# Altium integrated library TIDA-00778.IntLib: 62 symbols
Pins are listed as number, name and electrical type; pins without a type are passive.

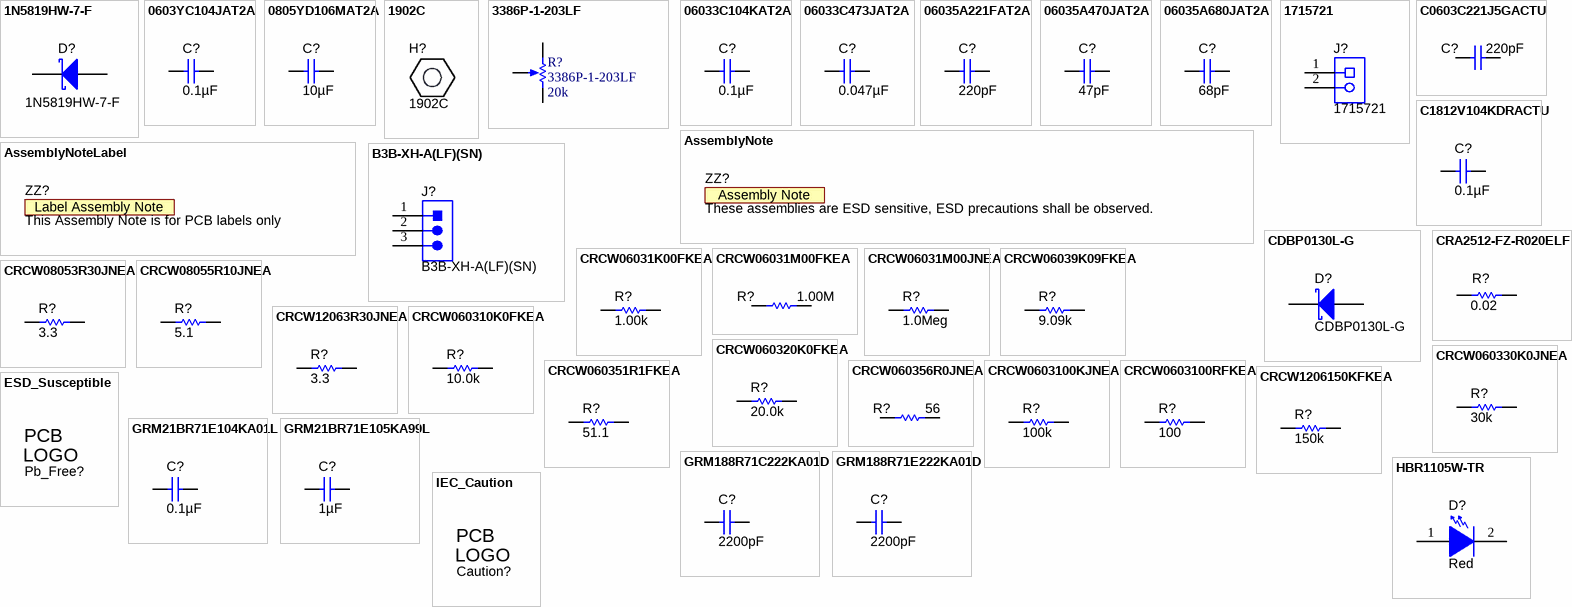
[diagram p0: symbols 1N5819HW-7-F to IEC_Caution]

## 1N5819HW-7-F
designator D?
Diode, Schottky, 40V, 1A, SOD-123; Manufacturer: Diodes Inc.; U/M: EA; Vf_V: 0.45; Value2: 0.45V; Io_A: 1; Vr_V: 40; TJmax_C: 125
signal-integrity model Diode
simulation model DI_1N5819HW
footprint SOD-123
pins: 1 K, 2 A

## 0603YC104JAT2A
designator C?  ValueDisplayed: 0.1µF  (hidden comment: 0603YC104JAT2A)
CAP, CERM, 0.1 µF, 16 V, +/- 5%, X7R, 0603; Manufacturer: AVX; Polarized: N; CompType: Capacitor; Value: 0.1uF; U/M: EA; Cap_F: 0.0000001; Tolerance_%: 5; ESR_ohm: 0.039; Value1: 0.039 ohm; VDC_V: 16; Value2: 16V; TaMin_C: -55; TaMax_C: 125; Cap_Case: 0603
signal-integrity model Cap
simulation model Cap
footprint 0603
footprint 0603M
footprint 0603L
footprint 0603_HV
footprint 0603S
pins: 1, 2

## 0805YD106MAT2A
designator C?  ValueDisplayed: 10µF  (hidden comment: 0805YD106MAT2A)
CAP, CERM, 10 µF, 16 V, +/- 20%, X5R, 0805; Manufacturer: AVX; Polarized: N; CompType: Capacitor; Value: 10uF; U/M: EA; Cap_F: 0.00001; Tolerance_%: 20; Value1: Unknown; VDC_V: 16; Value2: 16V; TaMin_C: -55; TaMax_C: 85; Cap_Case: 0805; SizeArea_mm2: 2.5; SizeAreaWB_mm2: 6.75; SizeX_mm: 2; SizeY_mm: 1.25; SizeZ_mm: 1.45; AEC Category: Q200
signal-integrity model Cap
simulation model Cap
footprint 0805_HV
footprint 0805_HV1
footprint 0805
footprint 0805M
footprint 0805L
pins: 1, 2

## 1902C
designator H?
Standoff, Hex, 0.5"L #4-40 Nylon; Manufacturer: Keystone; CompType: Hardware
footprint Keystone_1902C

## 3386P-1-203LF
designator R?  value 20k
TRIMMER, 20k ohm, 0.5W, TH; Manufacturer: Bourns; Sim Note: Enter the Resistance value and the set point into parameter fields.; SymbolCreator: a0412235
simulation model POT (Potentiometer)
footprint BOURNS_3386P
pins: 1 CCW, 2 WIPER, 3 CW
1 alternate drawing of the same symbol

## 06033C104KAT2A
designator C?  ValueDisplayed: 0.1µF  (hidden comment: 06033C104KAT2A)
CAP, CERM, 0.1 µF, 25 V, +/- 10%, X7R, 0603; Manufacturer: AVX; Polarized: N; CompType: Capacitor; Value: 0.1uF; U/M: EA; Cap_F: 0.0000001; Tolerance_%: 10; ESR_ohm: 0.05; Value1: 0.05 ohm; VDC_V: 25; Value2: 25V; TaMin_C: -55; TaMax_C: 125; Cap_Case: 0603
signal-integrity model Cap
simulation model Cap
footprint 0603
footprint 0603M
footprint 0603L
footprint 0603_HV
footprint 0603S
pins: 1, 2

## 06033C473JAT2A
designator C?  ValueDisplayed: 0.047µF  (hidden comment: 06033C473JAT2A)
CAP, CERM, 0.047 µF, 25 V, +/- 5%, X7R, 0603; Manufacturer: AVX; Polarized: N; CompType: Capacitor; Value: 0.047uF; U/M: EA; Cap_F: 0.000000047; Tolerance_%: 5; ESR_ohm: 0.052; Value1: 0.052 ohm; VDC_V: 25; Value2: 25V; TaMin_C: -55; TaMax_C: 125; Cap_Case: 0603; SizeArea_mm2: 1.28; SizeAreaWB_mm2: 4.68; SizeX_mm: 1.6; SizeY_mm: 0.8; SizeZ_mm: 1; AEC Category: Q200
signal-integrity model Cap
simulation model Cap
footprint 0603
footprint 0603M
footprint 0603L
footprint 0603_HV
footprint 0603S
pins: 1, 2

## 06035A221FAT2A
designator C?  ValueDisplayed: 220pF  (hidden comment: 06035A221FAT2A)
CAP, CERM, 220 pF, 50 V, +/- 1%, C0G/NP0, 0603; Manufacturer: AVX; Polarized: N; CompType: Capacitor; Value: 220pF; U/M: EA; Cap_F: 0.00000000022; Tolerance_%: 1; ESR_ohm: 0.083; Value1: 0.083 ohm; VDC_V: 50; Value2: 50V; TaMin_C: -55; TaMax_C: 125; Cap_Case: 0603
signal-integrity model Cap
simulation model Cap
footprint 0603
footprint 0603M
footprint 0603L
footprint 0603_HV
footprint 0603S
pins: 1, 2

## 06035A470JAT2A
designator C?  ValueDisplayed: 47pF  (hidden comment: 06035A470JAT2A)
CAP, CERM, 47 pF, 50 V, +/- 5%, C0G/NP0, 0603; Manufacturer: AVX; Polarized: N; CompType: Capacitor; Value: 47pF; U/M: EA; Cap_F: 0.000000000047; Tolerance_%: 5; ESR_ohm: 0.174; Value1: 0.174 ohm; VDC_V: 50; Value2: 50V; TaMin_C: -55; TaMax_C: 125; Cap_Case: 0603
signal-integrity model Cap
simulation model Cap
footprint 0603
footprint 0603M
footprint 0603L
footprint 0603_HV
footprint 0603S
pins: 1, 2

## 06035A680JAT2A
designator C?  ValueDisplayed: 68pF  (hidden comment: 06035A680JAT2A)
CAP, CERM, 68pF, 50V, +/-5%, C0G/NP0, 0603; Manufacturer: AVX; Polarized: N; CompType: Capacitor; U/M: EA; Cap_F: 0.000000000068; Tolerance_%: 5; ESR_Ohm: 0.144; Value1: 0.144 ohm; VDC_V: 50; TaMin_C: -55; TaMax_C: 125; Cap_Case: 0603
signal-integrity model Cap
simulation model Cap
footprint 0603
footprint 0603M
footprint 0603L
footprint 0603_HV
footprint 0603S
pins: 1, 2

## 1715721
designator J?
Conn Term Block, 2POS, 5.08mm, TH; Manufacturer: Phoenix Contact; SymbolCreator: a0412235; CompType: Terminal Block; U/M: EA; Value: 2x1
footprint PhoenixContact_1715721
pins: 1, 2

## AssemblyNote
designator ZZ?, comment These assemblies are ESD sensitive, ESD precautions shall be observed.  (no BOM)
SymbolCreator: codlsc; CompType: AssemblyNote
footprint AssemblyNote

## AssemblyNoteLabel
designator ZZ?, comment This Assembly Note is for PCB labels only  (no BOM)
SymbolCreator: a0412235
footprint AssemblyNoteLabel

## B3B-XH-A(LF)(SN)
designator J?
Header (Shrouded), 2.5mm, 3x1, Tin, TH; Manufacturer: JST Manufacturing; SymbolCreator: a0799628; Pitch_mm: 2.5; Gender: Male; Shrouded: Y; Row_Count: 1; Current_A: 3; Voltage_V: 250
footprint JST_B3B-XH-A
pins: 1, 2, 3
3 alternate drawings of the same symbol

## C0603C221J5GACTU
designator C?  ValueDisplayed: 220pF  (hidden comment: C0603C221J5GACTU)
CAP, CERM, 220 pF, 50 V, +/- 5%, C0G/NP0, 0603; Manufacturer: Kemet; Polarized: N; CompType: Capacitor; Value: 220pF; U/M: EA; Cap_F: 0.00000000022; Tolerance_%: 5; Value1: Unknown; VDC_V: 50; Value2: 50V; TaMin_C: -55; TaMax_C: 125; Cap_Case: 0603; SizeArea_mm2: 1.28; SizeAreaWB_mm2: 4.68; SizeX_mm: 1.6; SizeY_mm: 0.8; SizeZ_mm: 1; AEC Category: Q200
signal-integrity model Cap
simulation model Cap
footprint 0603
footprint 0603M
footprint 0603L
footprint 0603_HV
footprint 0603S
pins: 1, 2

## C1812V104KDRACTU
designator C?  ValueDisplayed: 0.1µF  (hidden comment: C1812V104KDRACTU)
CAP, CERM, 0.1 µF, 1000 V, +/- 10%, X7R, 1812; Manufacturer: Kemet; Polarized: N; CompType: Capacitor; Value: 0.1uF; U/M: EA; Cap_F: 0.0000001; Tolerance_%: 10; Value1: Unknown; VDC_V: 1000; Value2: 1000V; TaMin_C: -55; TaMax_C: 125; Cap_Case: 1812; SizeArea_mm2: 14.4; SizeAreaWB_mm2: 23.1; SizeX_mm: 4.5; SizeY_mm: 3.2; SizeZ_mm: 2.54; AEC Category: Q200
signal-integrity model Cap
simulation model Cap
footprint 1812_254
pins: 1, 2

## CDBP0130L-G
designator D?
Diode, Schottky, 30 V, 0.1 A, SOD-723; Manufacturer: Comchip Technology; U/M: EA; Vf_V: 0.35; Value: 30V; Value1: 0.1A; Value2: 0.35V; Io_A: 0.1; Vr_V: 30; TJmax_C: 125; SizeAreaWB_mm2: 3.84; SizeArea_mm2: 0.84; SizeX_mm: 1.4; SizeY_mm: 0.6; SizeZ_mm: 0.65; AEC Category: Q101
signal-integrity model Diode
footprint SOD-723
pins: 1 K, 2 A

## CRA2512-FZ-R020ELF
designator R?  ValueDisplayed: 0.02  (hidden comment: CRA2512-FZ-R020ELF)
RES, 0.02, 1%, 3 W, 2512; Manufacturer: Bourns; CompType: Resistor; Value: 0.02; Value_Code: R020; Tolerance_%: 1; Power_W: 3; Value2: 3W; TempCo: 75 ppm/C; EIA_Code: E96; U/M: EA
signal-integrity model Resistor
simulation model Resistor
footprint 2512
footprint 2512M
footprint 2512L
pins: 1, 2

## CRCW06031K00FKEA
designator R?  ValueDisplayed: 1.00k  (hidden comment: CRCW06031K00FKEA)
RES, 1.00 k, 1%, 0.1 W, 0603; Manufacturer: Vishay-Dale; CompType: Resistor; Value: 1.00k; Res_ohm: 1000; Value_Code: 1k00; Tolerance_%: 1; Power_W: 0.1; Value2: 0.1W; VDC_V: 75; TempCo: 100 ppm/C; EIA_Code: E96; U/M: EA
signal-integrity model Resistor
simulation model Resistor
footprint 0603
footprint 0603M
footprint 0603L
footprint 0603_HV
footprint 0603S
pins: 1, 2

## CRCW06031M00FKEA
designator R?  ValueDisplayed: 1.00M  (hidden comment: CRCW06031M00FKEA)
RES, 1.00 M, 1%, 0.1 W, 0603; Manufacturer: Vishay-Dale; CompType: Resistor; Value: 1.00Meg; Res_ohm: 1000000; Value_Code: 1M00; Tolerance_%: 1; Power_W: 0.1; Value2: 0.1W; VDC_V: 75; TempCo: 100 ppm/C; SizeArea_mm2: 1.28; SizeX_mm: 1.6; SizeY_mm: 0.8; EIA_Code: E96; U/M: EA; AEC Category: Q200
signal-integrity model Resistor
simulation model Resistor
footprint 0603
footprint 0603M
footprint 0603L
footprint 0603_HV
footprint 0603S
pins: 1, 2

## CRCW06031M00JNEA
designator R?  value 1.0Meg  (hidden comment: CRCW06031M00JNEA)
RES, 1.0Meg ohm, 5%, 0.1W, 0603; Manufacturer: Vishay-Dale; CompType: Resistor; Res_ohm: 1000000; Value_Code: 1M00; Tolerance_%: 5; Power_W: 0.1; VDC_V: 75; TempCo: 200 ppm/C; EIA_Code: E24; U/M: EA
signal-integrity model Resistor
simulation model Resistor
footprint 0603
footprint 0603M
footprint 0603L
footprint 0603_HV
footprint 0603S
pins: 1, 2

## CRCW06039K09FKEA
designator R?  ValueDisplayed: 9.09k  (hidden comment: CRCW06039K09FKEA)
RES, 9.09 k, 1%, 0.1 W, 0603; Manufacturer: Vishay-Dale; CompType: Resistor; Res_ohm: 9090; Value: 9.09k; Value_Code: 9k09; Tolerance_%: 1; Power_W: 0.1; Value2: 0.1W; VDC_V: 75; TempCo: 100 ppm/C; EIA_Code: E96; U/M: EA; SizeArea_mm2: 1.28; SizeX_mm: 1.6; SizeY_mm: 0.8; AEC Category: Q200
signal-integrity model Resistor
simulation model Resistor
footprint 0603
footprint 0603M
footprint 0603L
footprint 0603_HV
footprint 0603S
pins: 1, 2

## CRCW08053R30JNEA
designator R?  value 3.3  (hidden comment: CRCW08053R30JNEA)
RES, 3.3 ohm, 5%, 0.125W, 0805; Manufacturer: Vishay-Dale; CompType: Resistor; Value_Code: 3R30; Tolerance_%: 5; Power_W: 0.125; VDC_V: 150; TempCo: 200 ppm/C; EIA_Code: E24; U/M: EA
signal-integrity model Resistor
simulation model Resistor
footprint 0805_HV
footprint 0805
footprint 0805M
footprint 0805L
pins: 1, 2

## CRCW08055R10JNEA
designator R?  value 5.1  (hidden comment: CRCW08055R10JNEA)
RES, 5.1 ohm, 5%, 0.125W, 0805; Manufacturer: Vishay-Dale; CompType: Resistor; Value_Code: 5R10; Tolerance_%: 5; Power_W: 0.125; VDC_V: 150; TempCo: 200 ppm/C; EIA_Code: E24; U/M: EA
signal-integrity model Resistor
simulation model Resistor
footprint 0805_HV
footprint 0805
footprint 0805M
footprint 0805L
pins: 1, 2

## CRCW12063R30JNEA
designator R?  value 3.3  (hidden comment: CRCW12063R30JNEA)
RES, 3.3 ohm, 5%, 0.25W, 1206; Manufacturer: Vishay-Dale; CompType: Resistor; Value_Code: 3R30; Tolerance_%: 5; Power_W: 0.25; VDC_V: 200; TempCo: 200 ppm/C; EIA_Code: E24; U/M: EA
signal-integrity model Resistor
simulation model Resistor
footprint 1206
footprint 1206M
footprint 1206L
pins: 1, 2

## CRCW060310K0FKEA
designator R?  ValueDisplayed: 10.0k  (hidden comment: CRCW060310K0FKEA)
RES, 10.0 k, 1%, 0.1 W, 0603; Manufacturer: Vishay-Dale; CompType: Resistor; Value: 10.0k; Res_ohm: 10000; Value_Code: 10k0; Tolerance_%: 1; Power_W: 0.1; Value2: 0.1W; VDC_V: 75; TempCo: 100 ppm/C; EIA_Code: E96; U/M: EA; SizeArea_mm2: 1.28; SizeX_mm: 1.6; SizeY_mm: 0.8; AEC Category: Q200
signal-integrity model Resistor
simulation model Resistor
footprint 0603
footprint 0603M
footprint 0603L
footprint 0603_HV
footprint 0603S
pins: 1, 2

## CRCW060320K0FKEA
designator R?  value 20.0k  (hidden comment: CRCW060320K0FKEA)
RES, 20.0k ohm, 1%, 0.1W, 0603; Manufacturer: Vishay-Dale; CompType: Resistor; Res_ohm: 20000; Value_Code: 20k0; Tolerance_%: 1; Power_W: 0.1; VDC_V: 75; TempCo: 100 ppm/C; EIA_Code: E96; U/M: EA
signal-integrity model Resistor
simulation model Resistor
footprint 0603
footprint 0603M
footprint 0603L
footprint 0603_HV
footprint 0603S
pins: 1, 2

## CRCW060330K0JNEA
designator R?  ValueDisplayed: 30k  (hidden comment: CRCW060330K0JNEA)
RES, 30 k, 5%, 0.1 W, 0603; Manufacturer: Vishay-Dale; CompType: Resistor; Value: 30k; Res_ohm: 30000; Value_Code: 30k0; Tolerance_%: 5; Power_W: 0.1; Value2: 0.1W; VDC_V: 75; TempCo: 200 ppm/C; EIA_Code: E24; U/M: EA; SizeArea_mm2: 1.28; SizeX_mm: 1.6; SizeY_mm: 0.8; SizeZ_mm: 1; AEC Category: Q200
signal-integrity model Resistor
simulation model Resistor
footprint 0603
footprint 0603M
footprint 0603L
footprint 0603_HV
footprint 0603S
pins: 1, 2

## CRCW060351R1FKEA
designator R?  ValueDisplayed: 51.1  (hidden comment: CRCW060351R1FKEA)
RES, 51.1, 1%, 0.1 W, 0603; Manufacturer: Vishay-Dale; CompType: Resistor; Value: 51.1; Value_Code: 51R1; Tolerance_%: 1; Power_W: 0.1; Value2: 0.1W; VDC_V: 75; TempCo: 100 ppm/C; EIA_Code: E96; U/M: EA
signal-integrity model Resistor
simulation model Resistor
footprint 0603
footprint 0603M
footprint 0603L
footprint 0603_HV
footprint 0603S
pins: 1, 2

## CRCW060356R0JNEA
designator R?  value 56  (hidden comment: CRCW060356R0JNEA)
RES, 56 ohm, 5%, 0.1W, 0603; Manufacturer: Vishay-Dale; CompType: Resistor; Value_Code: 56R0; Tolerance_%: 5; Power_W: 0.1; VDC_V: 75; TempCo: 200 ppm/C; EIA_Code: E24; U/M: EA
signal-integrity model Resistor
simulation model Resistor
footprint 0603
footprint 0603M
footprint 0603L
footprint 0603_HV
pins: 1, 2

## CRCW0603100KJNEA
designator R?  ValueDisplayed: 100k  (hidden comment: CRCW0603100KJNEA)
RES, 100 k, 5%, 0.1 W, 0603; Manufacturer: Vishay-Dale; CompType: Resistor; Value: 100k; Res_ohm: 100000; Tolerance_%: 5; Power_W: 0.1; Value2: 0.1W; VDC_V: 75; TempCo: 200 ppm/C; EIA_Code: E24; U/M: EA; SizeArea_mm2: 1.28; SizeX_mm: 1.6; SizeY_mm: 0.8; SizeZ_mm: 1; AEC Category: Q200
signal-integrity model Resistor
simulation model Resistor
footprint 0603
footprint 0603M
footprint 0603L
footprint 0603_HV
footprint 0603S
pins: 1, 2

## CRCW0603100RFKEA
designator R?  ValueDisplayed: 100  (hidden comment: CRCW0603100RFKEA)
RES, 100, 1%, 0.1 W, 0603; Manufacturer: Vishay-Dale; CompType: Resistor; Value: 100; Value_Code: 100R; Tolerance_%: 1; Power_W: 0.1; Value2: 0.1W; VDC_V: 75; TempCo: 100 ppm/C; EIA_Code: E96; U/M: EA; SizeArea_mm2: 1.28; SizeX_mm: 1.6; SizeY_mm: 0.8; AEC Category: Q200
signal-integrity model Resistor
simulation model Resistor
footprint 0603
footprint 0603M
footprint 0603L
footprint 0603_HV
footprint 0603S
pins: 1, 2

## CRCW1206150KFKEA
designator R?  value 150k  (hidden comment: CRCW1206150KFKEA)
RES, 150k ohm, 1%, 0.25W, 1206; Manufacturer: Vishay-Dale; CompType: Resistor; Res_ohm: 150000; Tolerance_%: 1; Power_W: 0.25; VDC_V: 200; TempCo: 100 ppm/C; EIA_Code: E96; U/M: EA
signal-integrity model Resistor
simulation model Resistor
footprint 1206 (1206 from SM-752 data)
footprint 1206M
footprint 1206L
pins: 1, 2

## ESD_Susceptible
designator Pb_Free?, comment ESD Susceptible  (value not drawn)  (no BOM)
ESD Susceptible Symbol; SymbolCreator: a0412235
footprint ESD_Overlay_small
footprint ESD_Overlay_Medium
footprint ESD_Overlay_Small

## GRM21BR71E104KA01L
designator C?  ValueDisplayed: 0.1µF  (hidden comment: GRM21BR71E104KA01L)
CAP, CERM, 0.1 µF, 25 V, +/- 10%, X7R, 0805; Manufacturer: MuRata; Polarized: N; CompType: Capacitor; Value: 0.1uF; U/M: EA; Cap_F: 0.0000001; Tolerance_%: 10; Value1: Unknown; VDC_V: 25; Value2: 25V; TaMin_C: -55; TaMax_C: 125; Cap_Case: 0805
signal-integrity model Cap
simulation model Cap
footprint 0805_HV
footprint 0805
footprint 0805M
footprint 0805L
pins: 1, 2

## GRM21BR71E105KA99L
designator C?  ValueDisplayed: 1µF  (hidden comment: GRM21BR71E105KA99L)
CAP, CERM, 1uF, 25V, +/-10%, X7R, 0805; Manufacturer: MuRata; Polarized: N; CompType: Capacitor; U/M: EA; Cap_F: 0.000001; Tolerance_%: 10; Value1: Unknown; VDC_V: 25; TaMin_C: -55; TaMax_C: 125; Cap_Case: 0805
signal-integrity model Cap
simulation model Cap
footprint 0805_HV
footprint 0805
footprint 0805M
footprint 0805L
pins: 1, 2

## GRM188R71C222KA01D
designator C?  ValueDisplayed: 2200pF  (hidden comment: GRM188R71C222KA01D)
CAP, CERM, 2200pF, 16V, +/-10%, X7R, 0603; Manufacturer: MuRata; Polarized: N; CompType: Capacitor; U/M: EA; Cap_F: 0.0000000022; Tolerance_%: 10; Value1: Unknown; VDC_V: 16; TaMin_C: -55; TaMax_C: 125; Cap_Case: 0603
signal-integrity model Cap
simulation model Cap
footprint 0603
footprint 0603M
footprint 0603L
footprint 0603_HV
pins: 1, 2

## GRM188R71E222KA01D
designator C?  ValueDisplayed: 2200pF  (hidden comment: GRM188R71E222KA01D)
CAP, CERM, 2200 pF, 25 V, +/- 10%, X7R, 0603; Manufacturer: MuRata; Polarized: N; CompType: Capacitor; Value: 2200pF; U/M: EA; Cap_F: 0.0000000022; Tolerance_%: 10; Value1: Unknown; VDC_V: 25; Value2: 25V; TaMin_C: -55; TaMax_C: 125; Cap_Case: 0603
signal-integrity model Cap
simulation model Cap
footprint 0603
footprint 0603M
footprint 0603L
footprint 0603_HV
footprint 0603S
pins: 1, 2

## HBR1105W-TR
designator D?  value Red  (hidden comment: HBR1105W-TR)
LED, Red, SMD; Manufacturer: Stanley Electric Co., LTD; Vf_V: 1.7; Value2: 1.7V; Io_A: 0.02; Value1: W; U/M: EA
signal-integrity model Diode
footprint 1105W_Red
pins: 1 A, 2 K

## IEC_Caution
designator Caution?, comment CAUTION.  READ USER GUIDE BEFORE USE  (value not drawn)  (no BOM)
IEC 61010-1 Caution Warning; SymbolCreator: a0412235
footprint IEC_Caution_small
footprint IEC_Caution_Medium
footprint IEC_Caution_Small

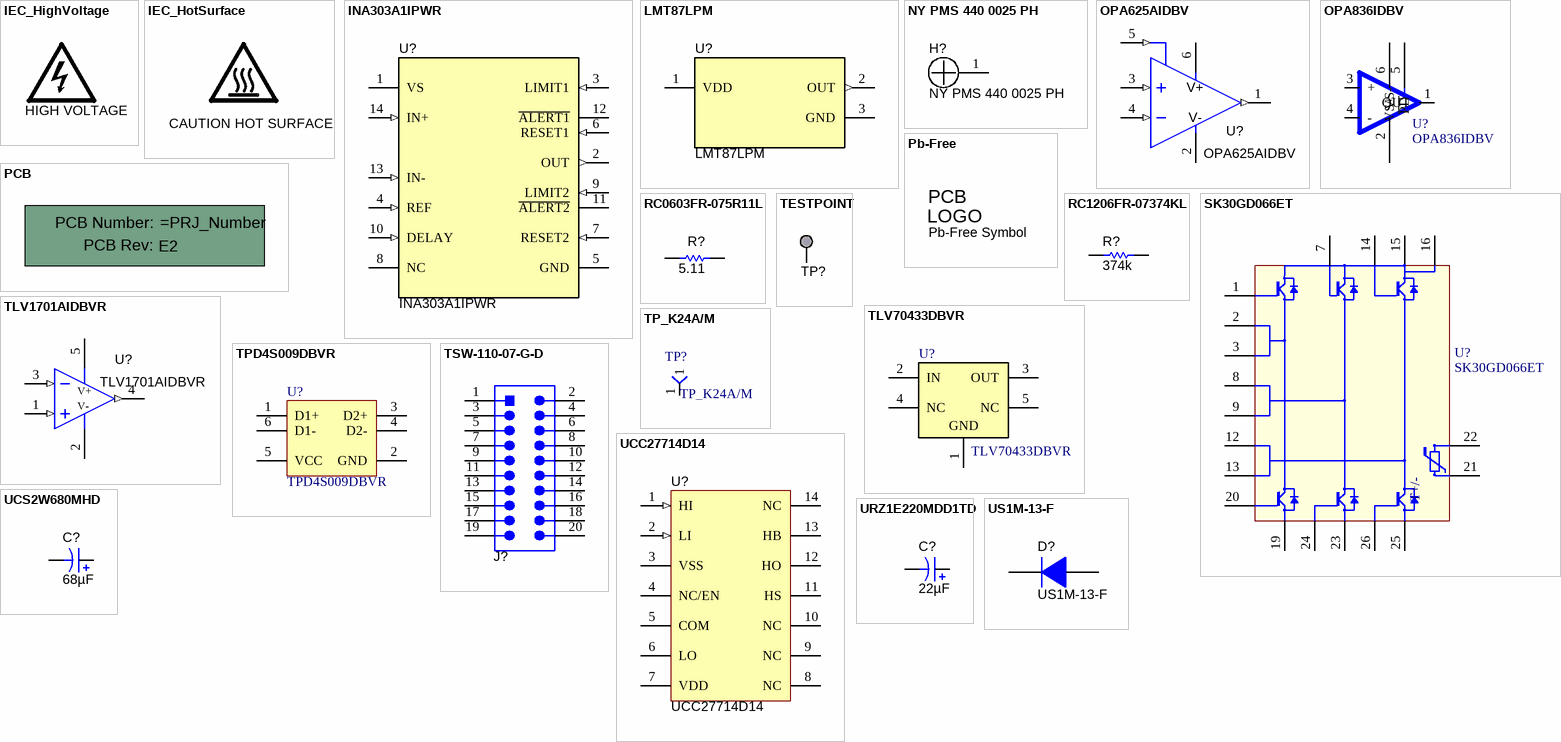
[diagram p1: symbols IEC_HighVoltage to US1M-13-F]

## IEC_HighVoltage
designator 1?, comment HIGH VOLTAGE  (no BOM)
IEC 61010-1 High Voltage Warning; SymbolCreator: a0412235
footprint IEC_HighVoltage_small
footprint IEC_HighVoltage_Medium
footprint IEC_HighVoltage_Small

## IEC_HotSurface
designator 3?, comment CAUTION HOT SURFACE  (no BOM)
IEC 61010-1 Hot Surface Warning; SymbolCreator: a0412235
footprint IEC_HotSurface_small
footprint IEC_HotSurface_Medium
footprint IEC_HotSurface_Small

## INA303A1IPWR
designator U?
36-V, High-Speed, Bi-Directional, Zero-Drift, Voltage-Output, Current-Shunt Monitor with Multi-Alert High-Speed, Overcurrent Comparator, PW0014A; Manufacturer: Texas Instruments; SymbolCreator: Altium; SizeArea_mm2: 32; SizeAreaWB_mm2: 58.8; SizeX_mm: 6.4; SizeY_mm: 5; SizeZ_mm: 1.2; CompType: IC; U/M: EA
footprint PW0014A_N
footprint PW0014A_M
footprint PW0014A_L
pins: 1 VS (power), 2 OUT (out), 3 LIMIT1 (in), 4 REF (in), 5 GND (power), 6 RESET1 (in), 7 RESET2 (in), 8 NC, 9 LIMIT2 (in), 10 DELAY (in), 11 ~{ALERT2} (oc), 12 ~{ALERT1} (oc), 13 IN- (in), 14 IN+ (in)

## LMT87LPM
designator U?
Analog Temperature Sensors with Class-AB Output, LP0003A; Manufacturer: Texas Instruments; SymbolCreator: Altium; SizeArea_mm2: 18.4; SizeAreaWB_mm2: 39.76; SizeX_mm: 3.68; SizeY_mm: 5; SizeZ_mm: 9.33; CompType: IC; U/M: EA
footprint LP0003A
footprint LP0003A_straight
pins: 1 VDD (power), 2 OUT (out), 3 GND (power)

## NY PMS 440 0025 PH
designator H?
Machine Screw, Round, #4-40 x 1/4, Nylon, Philips panhead; Manufacturer: B&F Fastener Supply; CompType: Hardware; SymbolCreator: codlsc; U/M: EA
footprint NY PMS 440 0025 PH
footprint NY PMS 440 0025 PH_3Donly
pins: 1

## OPA625AIDBV
designator U?
High Bandwidth, High Precision, Low Noise and Distortion Amplifier with Ultra-Fast Transition time Low Power mode, DBV0006A; Manufacturer: Texas Instruments; SymbolCreator: Altium; CompType: IC; U/M: EA
footprint DBV0006A_N (SOT23, 6-Leads, Body 2.9x1.6mm, Pitch 0.95mm, Lead Span 2.8mm, IPC Medium Density)
footprint DBV0006A_M
footprint DBV0006A_L
pins: 1 OUT (out), 2 V- (power), 3 IN+ (in), 4 IN- (in), 5 MODE (in), 6 V+ (power)

## OPA836IDBV
designator U?
IC, R-R Out, Negative Rail In, VFB Op Amp; Manufacturer: TI; Alternate Manufacturer: None; Area: 31500
footprint SOT23-6
pins: 1 OUT, 2 VS-, 3 +, 4 -, 5 ~{PD}, 6 VS+

## Pb-Free
designator Pb?, comment Pb-Free Symbol  (no BOM)
SymbolCreator: a0412235
footprint Pb-Free_Overlay_Medium
footprint Pb-Free_Overlay_Small

## PCB
designator LBL?, comment Printed Circuit Board  (value not drawn)  (mechanical)
Manufacturer: Any; SymbolCreator: a0412235; CompType: PCB
footprint Label_650x200 (Thermal Transfer Label)
1 alternate drawing of the same symbol

## RC0603FR-075R11L
designator R?  ValueDisplayed: 5.11  (hidden comment: RC0603FR-075R11L)
RES, 5.11, 1%, 0.1 W, 0603; Manufacturer: Yageo America; CompType: Resistor; Value: 5.11; Value_Code: 5R11; Tolerance_%: 1; Power_W: 0.1; Value2: 0.1W; VDC_V: 150; TempCo: 200 ppm/C; EIA_Code: E96; U/M: EA
signal-integrity model Resistor
simulation model Resistor
footprint 0603
footprint 0603M
footprint 0603L
footprint 0603_HV
footprint 0603S
pins: 1, 2

## RC1206FR-07374KL
designator R?  ValueDisplayed: 374k  (hidden comment: RC1206FR-07374KL)
RES, 374 k, 1%, 0.25 W, 1206; Manufacturer: Yageo America; CompType: Resistor; Value: 374k; Res_ohm: 374000; Tolerance_%: 1; Power_W: 0.25; Value2: 0.25W; VDC_V: 200; TempCo: 100 ppm/C; EIA_Code: E96; U/M: EA; SizeArea_mm2: 5.12; SizeX_mm: 3.2; SizeY_mm: 1.6; SizeZ_mm: 1.35; AEC Category: Q200
signal-integrity model Resistor
simulation model Resistor
footprint 1206
footprint 1206M
footprint 1206L
pins: 1, 2

## SK30GD066ET
designator U?
MODULE,THRU-19PIN; Manufacturer: SEMIKRON; CompType: MODULE-19P; SymbolCreator: "x0199378"
footprint MODULE_SK30GD066ET (MODULE, TH-19P)
pins: 1, 2, 3, 7, 8, 9, 12, 13, 14, 15, 16, 19, 20, 21, 22, 23, 24, 25, 26

## TESTPOINT
designator TP?  (value not drawn)  (no BOM)
TEST POINT.  No entry in BOM.
footprint TESTPOINT
footprint TP_VIA_018RND008
footprint TP_VIA_060RND040
footprint TP_25MIL-SMT
footprint TP_50MIL-25MILHOLE
footprint TP_60MIL-SMT
pins: 1

## TLV1701AIDBVR
designator U?
2.2-V to 36-V, microPower Comparator, DBV0005A; Alternate PartNumber: TLV1701AIDBVT; Manufacturer: Texas Instruments; SizeArea_mm2: 8.12; SizeAreaWB_mm2: 14.82; SizeX_mm: 2.8; SizeY_mm: 2.9; SizeZ_mm: 1.45; CompType: IC; U/M: EA; Sim Note: Shutdown not modeled
footprint DBV0005A_N
footprint DBV0005A_M
footprint DBV0005A_L
pins: 1 IN+ (in), 2 V- (power), 3 IN- (in), 4 OUT (out), 5 V+ (power)
1 alternate drawing of the same symbol

## TLV70433DBVR
designator U?
Single Output LDO, 150 mA, Fixed 3.3 V Output, 2.5 to 24 V Input, with Ultra-Low IQ, 5-pin SOT-23 (DBV), -40 to 125 degC, Green (RoHS & no Sb/Br); Manufacturer: Texas Instruments; Alternate PartNumber: Equivalent; Accuracy(%): 2; Fixed Output Options(V): 3.3; Iout(Max)(A): 0.15; Iq(Typ)(mA): 0.003; SubFamily: Single Channel LDO; Vdo(Typ)(mV): 400; Vin(Max)(V): 24; Vin(Min)(V): 2.5
footprint DBV0005A_N (SOT23, 5-Leads, Body 2.9x1.6mm, Pitch 0.95mm, IPC Medium Density)
footprint DBV0005A_L (SOT23, 5-Leads, Body 2.9x1.6mm, Pitch 0.95mm, IPC High Density)
footprint DBV0005A_M (SOT23, 5-Leads, Body 2.9x1.6mm, Pitch 0.95mm, IPC Low Density)
pins: 1 GND (power) "Ground", 2 IN (power) "Unregulated input voltage", 3 OUT (power) "Regulated output voltage. Any capacitor 1 uF or greater between this pin and ground is needed for stability", 4 NC "No connection. This pin can be left open or tied to ground for improved thermal performance", 5 NC "No connection. This pin can be left open or tied to ground for improved thermal performance"

## TP_K24A/M
designator TP?
Pin, Thru Hole, Tin Plate, for 0.062 PCB's; Manufacturer: Vector; PartNumber: K24A/M; area: 0.001 inch; Value: K24A/M
footprint HOLE-70X43
pins: 1

## TPD4S009DBVR
designator U?
ESD Solution for High-Speed Differential Interface, 4 Channels, -40 to +85 degC, 6-pin SOT-32 (DBV), Green (RoHS & no Sb/Br); Manufacturer: Texas Instruments; Alternate Manufacturer: None; Alternate PartNumber: Equivalent; Breakdown Voltage(Min)(V): 9; Differential Capacitance(pF): 0.05; IEC 61000-4-2 Contact(+/- kV): 8; IO Capacitance(Typ)(pF): 0.8; IO Leakage Current(nA): 10
footprint DBV0006A_N (SOT23, 6-Leads, Body 2.9x1.6mm, Pitch 0.95mm, Lead Span 2.8mm, IPC Medium Density)
footprint DBV0006A_L (SOT23, 6-Leads, Body 2.9x1.6mm, Pitch 0.95mm, Lead Span 2.8mm, IPC High Density)
footprint DBV0006A_M (SOT23, 6-Leads, Body 2.9x1.6mm, Pitch 0.95mm, Lead Span 2.8mm, IPC Low Density)
pins: 1 D1+ "High-speed ESD clamp provides ESD protection to the high-speed differential data line.", 2 GND (power) "Ground", 3 D2+ "High-speed ESD clamp provides ESD protection to the high-speed differential data line.", 4 D2- "High-speed ESD clamp provides ESD protection to the high-speed differential data line.", 5 VCC (power) "Supply", 6 D1- "High-speed ESD clamp provides ESD protection to the high-speed differential data line."

## TSW-110-07-G-D
designator J?  (value not drawn)
Header, 100mil, 10x2, Gold, TH; Manufacturer: Samtec; SymbolCreator: a0412235; Pitch_mm: 2.54; Gender: Male; Shrouded: N; Row_Count: 2; Current_A: 6.3; Voltage_V: 550; Cert_CSA: Y
footprint TSW-110-07-G-D
pins: 1, 2, 3, 4, 5, 6, 7, 8, 9, 10, 11, 12, 13, 14, 15, 16, 17, 18, 19, 20

## UCC27714D14
designator U?
High-Speed Low-side Gate Driver Device, D0014A; Alternate Manufacturer: None; Manufacturer: Texas Instruments; SymbolCreator: a0411947; CompType: IC; U/M: EA
footprint D0014A_N
footprint D0014A_M
footprint D0014A_L
pins: 1 HI (in), 2 LI (in), 3 VSS (power), 4 NC/EN, 5 COM (power), 6 LO (power), 7 VDD (power), 8 NC, 9 NC, 10 NC, 11 HS (power), 12 HO (power), 13 HB (power), 14 NC

## UCS2W680MHD
designator C?  ValueDisplayed: 68µF  (hidden comment: UCS2W680MHD)
CAP, AL, 68 µF, 450 V, +/- 20%, TH; Manufacturer: Nichicon; Polarized: Y; CompType: Capacitor; Value: 68uF; U/M: EA; Cap_F: 0.000068; Tolerance_%: 20; Value1: Unknown; VDC_V: 450; Value2: 450V; IRMS_A: 1.575; TaMin_C: -25; TaMax_C: 105; Cap_Case: 18x31.5mm; AEC Category: Q200; AEC Qualified: N
signal-integrity model Cap
simulation model Cap
footprint CS_1800x3150
footprint CS_1800x3150_HorizontalUp
footprint CS_1800x3150_HorizontalDown
pins: 1 +, 2 -

## URZ1E220MDD1TD
designator C?  ValueDisplayed: 22µF  (hidden comment: URZ1E220MDD1TD)
CAP, AL, 22 µF, 25 V, +/- 20%, TH; Manufacturer: Nichicon; Polarized: Y; CompType: Capacitor; Value: 22uF; U/M: EA; Cap_F: 0.000022; Tolerance_%: 20; Value1: Unknown; VDC_V: 25; Value2: 25V; IRMS_A: 0.055; TaMin_C: -55; TaMax_C: 105; Cap_Case: 5x9mm; AEC Category: Q200
signal-integrity model Cap
simulation model Cap
footprint RZ_500x900
pins: 1 +, 2 -

## US1M-13-F
designator D?
Diode, Ultrafast, 1000V, 1A, SMA; Manufacturer: Diodes Inc.; U/M: EA; Vf_V: 1.7; Value2: 1.7V; Io_A: 1; Vr_V: 1000; TJmax_C: 150; RJC_CperW: 30
signal-integrity model Diode
footprint SMA
pins: 1 K, 2 A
